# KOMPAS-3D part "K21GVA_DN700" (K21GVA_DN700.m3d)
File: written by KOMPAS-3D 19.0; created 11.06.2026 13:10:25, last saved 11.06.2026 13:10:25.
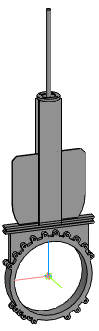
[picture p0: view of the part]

Document properties: Автор: Энергия; Полное имя файла: Z:\3.Личные\kachalov\001_3d для проектировщиков\2.5 Тип_K21GVA. Задвижка\_stp\_stp_K21GVA_DN50-DN1000_с фланцем\K21GVA_DN700.m3d

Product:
- Part/product: K21GVA_DN700

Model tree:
1. Операция без истории:1  (labels: K21GVA_DN700)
